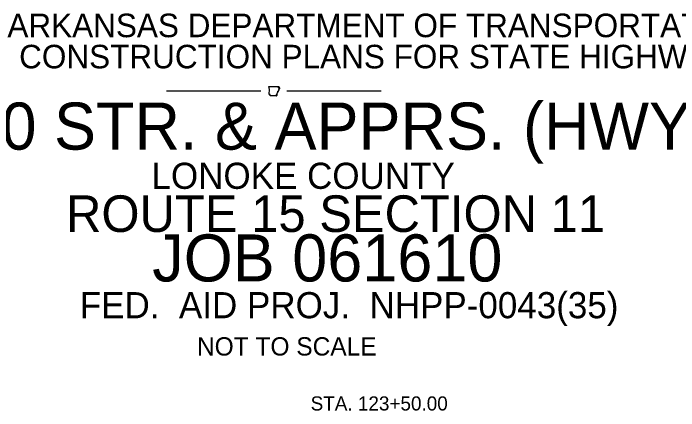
# Model space of a CAD drawing. Extents: x 1127717 to 1741049, y 2026793 to 2244711.
# Drawn here: x 1289221 to 1352785, y 2118754 to 2156746 of the extents above; entities that cross this region are included whole.
import ezdxf

# ---------------------------------------------------------------- set-up
doc = ezdxf.new("R2010")
doc.units = 0
doc.layers.add('R_Draft', color=7, linetype='Continuous')

msp = doc.modelspace()

# ---------------------------------------------------------------- linework, layer by layer
at = {"layer": 'R_Draft'}
for p, q in [((1303860.42359432, 2149337.5563738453), (1312860.4235955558, 2149337.5563738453)), ((1315360.42359432, 2149337.5563738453), (1324360.4235955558, 2149337.5563738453))]:
    msp.add_line(p, q, dxfattribs=at)
for points in [[(1313644.6151949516, 2149753.404178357), (1313917.4839450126, 2149753.2354283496), (1314156.9401949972, 2149753.7416783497), (1314439.4276950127, 2149758.129178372), (1314570.3776949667, 2149761.166678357)], [(1313664.358944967, 2149015.1229283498), (1313679.5464450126, 2149472.9416783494), (1313644.6151949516, 2149753.404178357)], [(1314529.8776949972, 2149629.372928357), (1314657.9589450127, 2149635.9541783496)], [(1314376.483944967, 2148850.4229283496), (1313758.015194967, 2148851.435428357), (1313757.6776950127, 2148987.9541783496)]]:
    msp.add_lwpolyline(points, dxfattribs=at)
for points in [[(1314570.3776949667, 2149761.166678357), (1314571.2214449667, 2149753.7416783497), (1314573.5839449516, 2149749.860428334), (1314573.9214450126, 2149742.7729283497), (1314576.7901950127, 2149739.7354283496), (1314581.6839449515, 2149736.697928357), (1314586.0714450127, 2149731.8041783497), (1314587.0839450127, 2149726.0666783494), (1314585.733944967, 2149720.160428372), (1314585.3964450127, 2149713.579178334), (1314584.7214449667, 2149707.841678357), (1314583.7089450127, 2149702.6104283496), (1314579.6589449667, 2149698.391678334), (1314575.7776950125, 2149695.3541783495), (1314572.2339450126, 2149691.8104283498), (1314569.7026950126, 2149688.0979283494), (1314565.3151949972, 2149684.047928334), (1314560.9276950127, 2149679.8291783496), (1314557.3839449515, 2149676.1166783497), (1314553.8401950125, 2149671.3916783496), (1314552.1526949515, 2149666.1604283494), (1314548.2714449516, 2149662.447928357), (1314545.233944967, 2149659.0729283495), (1314541.1839450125, 2149654.516678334), (1314539.1589449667, 2149649.9604283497), (1314535.2776949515, 2149644.7291783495), (1314534.4339449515, 2149639.666678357), (1314531.9026949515, 2149635.6166783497), (1314531.733944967, 2149634.9416783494)], [(1314518.5714450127, 2149306.2166783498), (1314514.6901949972, 2149301.322928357), (1314508.9526950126, 2149304.3604283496), (1314508.9526950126, 2149308.4104283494), (1314509.7964450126, 2149312.629178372), (1314507.7714450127, 2149315.3291783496), (1314504.2276950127, 2149314.147928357), (1314504.2276950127, 2149308.916678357), (1314503.8901950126, 2149303.8541783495), (1314502.8776949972, 2149296.5979283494), (1314505.2401949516, 2149294.404178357), (1314510.6401950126, 2149293.729178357), (1314514.5214449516, 2149292.716678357), (1314516.8839450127, 2149288.8354283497), (1314516.7151950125, 2149284.110428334), (1314514.8589450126, 2149279.5541783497), (1314512.1589449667, 2149275.8416783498), (1314507.9401949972, 2149274.4916783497), (1314504.5651949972, 2149276.6854283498), (1314503.2151949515, 2149281.0729283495), (1314501.6964450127, 2149284.9541783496), (1314498.827694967, 2149287.8229283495), (1314495.7901950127, 2149284.616678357), (1314495.1151950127, 2149278.7104283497), (1314495.2839449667, 2149273.6479283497), (1314495.2839449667, 2149266.7291783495), (1314499.671444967, 2149262.1729283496), (1314502.3714449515, 2149256.9416783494), (1314501.5276949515, 2149252.2166783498), (1314498.3214449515, 2149246.647928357), (1314496.9714449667, 2149241.7541783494), (1314495.6214450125, 2149235.1729283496), (1314495.7901950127, 2149227.916678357), (1314494.608944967, 2149220.8291783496), (1314492.2464449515, 2149216.1041783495), (1314487.858944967, 2149212.2229283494), (1314484.9901949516, 2149209.691678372), (1314482.6276949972, 2149207.1604283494), (1314481.4464449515, 2149202.097928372), (1314480.6026949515, 2149198.5541783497), (1314477.3964450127, 2149194.3354283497), (1314474.8651949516, 2149193.9979283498), (1314472.8401949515, 2149195.685428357), (1314472.1651950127, 2149198.5541783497), (1314472.1651950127, 2149201.422928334), (1314470.8151949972, 2149204.291678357), (1314466.5964449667, 2149205.4729283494), (1314463.2214449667, 2149205.3041783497), (1314461.7026950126, 2149202.9416783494), (1314463.8964450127, 2149196.3604283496), (1314464.7401950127, 2149192.1416783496), (1314463.5589449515, 2149186.4041783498), (1314464.233944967, 2149185.7291783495), (1314458.1589449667, 2149182.5229283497), (1314453.2651950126, 2149182.0166783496), (1314449.2151949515, 2149180.835428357), (1314445.3339449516, 2149178.3041783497), (1314443.4776950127, 2149174.591678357), (1314440.7776949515, 2149171.5541783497), (1314438.4151949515, 2149168.685428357), (1314435.2089450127, 2149167.3354283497), (1314431.6651950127, 2149168.010428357), (1314426.9401949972, 2149168.5166783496), (1314424.2401949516, 2149165.141678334), (1314425.0839449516, 2149160.247928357), (1314428.2901950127, 2149157.379178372), (1314433.0151950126, 2149156.0291783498), (1314437.9089449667, 2149156.3666783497), (1314442.6339450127, 2149156.8729283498), (1314447.0214450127, 2149154.5104283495), (1314446.1776949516, 2149149.954178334), (1314441.9589450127, 2149147.7604283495), (1314435.7151950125, 2149147.0854283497), (1314430.6526950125, 2149147.591678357), (1314424.5776950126, 2149146.2416783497), (1314421.5401949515, 2149142.360428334), (1314423.2276949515, 2149136.4541783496), (1314429.8089450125, 2149134.0916783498), (1314432.8464449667, 2149128.522928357), (1314433.0151950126, 2149123.291678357), (1314430.8214450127, 2149116.372928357), (1314427.7839449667, 2149113.166678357), (1314421.8776949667, 2149111.816678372), (1314417.3214449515, 2149110.9729283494), (1314416.6464449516, 2149103.2104283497), (1314414.6214449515, 2149099.3291783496), (1314411.077694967, 2149098.147928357), (1314406.015194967, 2149100.6791783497), (1314402.9776950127, 2149101.8604283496), (1314399.265194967, 2149103.5479283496), (1314394.5401949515, 2149106.416678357), (1314390.9964450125, 2149105.910428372), (1314392.0089449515, 2149098.485428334), (1314392.3464449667, 2149098.147928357), (1314396.3964449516, 2149092.5791783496), (1314400.4464450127, 2149088.1916783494), (1314402.3026949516, 2149082.9604283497)], [(1314591.8089449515, 2149473.4479283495), (1314592.4839450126, 2149468.5541783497), (1314589.6151950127, 2149463.322928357), (1314588.6026949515, 2149458.091678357), (1314589.108944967, 2149452.8604283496), (1314583.7089450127, 2149449.9916783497), (1314578.9839450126, 2149446.616678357), (1314581.6839449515, 2149442.5666783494), (1314586.7464450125, 2149438.854178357), (1314591.8089449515, 2149435.9854283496), (1314595.0151950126, 2149433.116678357), (1314595.8589450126, 2149426.197928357), (1314596.7026950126, 2149421.810428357), (1314598.3901950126, 2149415.7354283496), (1314599.0651949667, 2149411.5166783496), (1314596.0276949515, 2149406.4541783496), (1314592.4839450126, 2149405.4416783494), (1314588.7714450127, 2149406.622928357), (1314584.3839450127, 2149406.9604283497), (1314580.8401949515, 2149403.585428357), (1314578.3089450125, 2149398.8604283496), (1314575.7776950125, 2149394.1354283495), (1314573.9214450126, 2149390.0854283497), (1314572.0651949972, 2149385.6979283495), (1314568.3526949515, 2149380.635428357), (1314563.7964450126, 2149379.791678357), (1314558.3964450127, 2149378.441678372), (1314555.1901949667, 2149374.729178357), (1314555.6964450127, 2149368.4854283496), (1314558.733944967, 2149364.266678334), (1314561.0964449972, 2149359.0354283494), (1314562.7839449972, 2149354.4791783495), (1314561.9401949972, 2149348.7416783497), (1314559.577694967, 2149344.522928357), (1314556.5401949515, 2149341.9916783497), (1314555.1901949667, 2149336.591678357), (1314552.9964449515, 2149332.5416783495), (1314550.9714449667, 2149331.1916783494), (1314546.921444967, 2149331.529178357), (1314542.5339449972, 2149332.372928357), (1314538.8214449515, 2149332.0354283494), (1314535.2776949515, 2149330.1791783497), (1314531.733944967, 2149331.3604283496), (1314528.0214450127, 2149335.410428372), (1314524.983944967, 2149338.447928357), (1314521.6089450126, 2149339.6291783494), (1314518.0651949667, 2149337.7729283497), (1314517.390194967, 2149332.2041783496), (1314519.0776950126, 2149326.4666783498), (1314520.5964449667, 2149318.7041783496), (1314519.0776950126, 2149313.979178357), (1314518.5714450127, 2149306.2166783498)], [(1314656.1026949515, 2149635.7854283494), (1314657.9589450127, 2149635.9541783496), (1314663.6964450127, 2149629.8791783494), (1314666.2276950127, 2149624.816678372), (1314669.9401949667, 2149621.9479283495), (1314674.1589449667, 2149620.4291783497), (1314677.3651950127, 2149616.547928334), (1314679.5589449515, 2149612.3291783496), (1314678.3776949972, 2149608.6166783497), (1314673.6526950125, 2149608.2791783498), (1314668.4214450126, 2149607.4354283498), (1314663.358944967, 2149607.6041783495), (1314659.3089450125, 2149604.229178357), (1314663.0214449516, 2149599.6729283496), (1314667.9151950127, 2149595.454178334), (1314669.2651950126, 2149590.8979283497), (1314666.5651949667, 2149586.5104283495), (1314661.1651949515, 2149584.1479283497), (1314655.9339449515, 2149582.122928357), (1314651.2089450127, 2149578.0729283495), (1314649.015194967, 2149574.1916783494), (1314643.7839449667, 2149572.504178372), (1314638.3839450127, 2149570.9854283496), (1314633.6589449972, 2149570.4791783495), (1314628.2589449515, 2149569.466678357), (1314623.0276949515, 2149566.935428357), (1314620.8339450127, 2149562.5479283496), (1314621.5089450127, 2149556.3041783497), (1314621.3401949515, 2149549.722928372), (1314626.9089449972, 2149547.529178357), (1314631.8026949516, 2149547.3604283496), (1314636.5276950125, 2149544.8291783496), (1314636.0214449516, 2149541.1166783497), (1314632.4776949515, 2149536.3916783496), (1314628.2589449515, 2149532.6791783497), (1314624.0401949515, 2149530.822928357), (1314620.1589449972, 2149527.2791783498), (1314621.5089450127, 2149523.7354283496), (1314625.0526950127, 2149521.3729283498), (1314627.5839450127, 2149517.4916783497), (1314627.2464449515, 2149513.947928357), (1314623.1964449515, 2149511.4166783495), (1314618.8089449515, 2149512.4291783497), (1314615.6026950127, 2149516.6479283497), (1314611.890194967, 2149517.997928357), (1314608.6839450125, 2149519.5166783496), (1314604.9714449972, 2149517.3229283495), (1314604.9714449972, 2149512.4291783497), (1314603.6214450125, 2149507.197928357), (1314604.8026949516, 2149503.3166783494), (1314606.3214450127, 2149497.9166783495), (1314606.1526950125, 2149493.8666783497), (1314604.8026949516, 2149488.1291783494), (1314601.9339450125, 2149482.222928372), (1314598.5589450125, 2149480.3666783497), (1314597.2089450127, 2149486.779178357), (1314596.5339449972, 2149492.010428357), (1314594.5089449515, 2149495.0479283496), (1314591.8089449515, 2149495.216678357), (1314588.265194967, 2149492.685428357), (1314584.3839450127, 2149488.8041783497), (1314579.4901949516, 2149484.585428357), (1314576.6214450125, 2149480.3666783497), (1314578.1401950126, 2149475.1354283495), (1314581.8526950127, 2149473.7854283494), (1314584.7214449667, 2149474.7979283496), (1314586.2401950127, 2149478.1729283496), (1314589.108944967, 2149478.6791783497), (1314591.8089449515, 2149473.4479283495)], [(1313757.6776950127, 2148987.9541783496), (1313758.3526949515, 2148987.616678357), (1313755.1464450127, 2148989.810428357), (1313750.7589450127, 2148992.0041783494), (1313745.8651949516, 2148992.341678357), (1313739.6214450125, 2148993.1854283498), (1313734.3901950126, 2148993.691678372), (1313728.9901950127, 2148997.2354283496), (1313723.2526949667, 2148993.5229283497), (1313716.8401950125, 2148990.822928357), (1313713.1276949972, 2148993.8604283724), (1313708.2339450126, 2148991.8354283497), (1313704.8589450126, 2148992.847928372), (1313698.952694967, 2148988.7979283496), (1313693.3839450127, 2148990.3166783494), (1313689.3339449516, 2148989.135428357), (1313684.2714449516, 2148989.304178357), (1313683.2589449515, 2148995.041678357), (1313678.3651950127, 2148995.885428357), (1313674.1464449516, 2148998.247928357), (1313671.2776949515, 2149004.154178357), (1313669.2526949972, 2149008.7104283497), (1313664.358944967, 2149015.1229283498)], [(1314402.3026949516, 2149082.9604283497), (1314400.6151949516, 2149079.0791783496), (1314398.7589450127, 2149072.3291783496), (1314399.265194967, 2149066.5916783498), (1314401.7964450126, 2149061.697928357), (1314405.8464449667, 2149058.997928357), (1314410.233944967, 2149055.116678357), (1314409.8964450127, 2149049.2104283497), (1314407.3651950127, 2149047.0166783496), (1314401.4589449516, 2149048.5354283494), (1314396.9026950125, 2149050.560428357), (1314393.0214449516, 2149049.3791783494), (1314387.7901949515, 2149046.847928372), (1314383.9089449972, 2149046.3416783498), (1314384.077694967, 2149038.2416783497), (1314389.3089449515, 2149032.5041783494), (1314393.8651949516, 2149032.5041783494), (1314399.0964449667, 2149031.829178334), (1314400.9526950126, 2149025.7541783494), (1314397.9151950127, 2149020.6916783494), (1314392.8526949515, 2149018.1604283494), (1314386.4401949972, 2149021.1979283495), (1314381.8839450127, 2149024.4041783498), (1314377.327694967, 2149027.4416783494), (1314371.5901950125, 2149028.9604283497), (1314368.3839450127, 2149028.2854283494), (1314366.8651949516, 2149021.1979283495), (1314369.5651949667, 2149014.7854283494), (1314373.9526950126, 2149010.397928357), (1314378.0026949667, 2149004.6604283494), (1314377.327694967, 2149000.441678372), (1314374.2901950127, 2148999.2604283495), (1314368.890194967, 2148998.0791783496), (1314365.6839450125, 2148996.3916783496), (1314364.8401950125, 2148995.041678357), (1314366.5276950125, 2148989.304178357), (1314368.046444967, 2148983.060428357), (1314368.046444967, 2148978.3354283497), (1314366.1901949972, 2148973.947928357), (1314363.3214449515, 2148967.197928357), (1314363.6589449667, 2148962.8104283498), (1314365.6839450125, 2148960.7854283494), (1314368.2151950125, 2148961.4604283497), (1314371.5901950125, 2148963.8229283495), (1314373.7839449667, 2148966.522928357), (1314375.640194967, 2148969.8979283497), (1314379.1839450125, 2148972.7666783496), (1314383.5714450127, 2148970.2354283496), (1314384.5839450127, 2148965.004178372), (1314382.0526950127, 2148960.447928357), (1314378.5089450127, 2148958.4229283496), (1314374.1214449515, 2148956.7354283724), (1314370.9151950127, 2148953.0229283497), (1314371.7589450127, 2148948.6354283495), (1314374.2901950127, 2148946.2729283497), (1314380.5339449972, 2148947.4541783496), (1314384.7526949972, 2148949.3104283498), (1314387.1151949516, 2148951.6729283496), (1314389.9839450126, 2148954.5416783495), (1314391.5026949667, 2148957.410428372), (1314393.6964449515, 2148960.447928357), (1314397.577694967, 2148961.291678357), (1314399.4339450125, 2148958.760428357), (1314398.7589450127, 2148953.0229283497), (1314396.3964449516, 2148947.622928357), (1314393.1901949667, 2148943.066678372), (1314389.6464450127, 2148939.8604283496), (1314385.2589450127, 2148932.9416783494), (1314386.1026950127, 2148926.5291783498), (1314387.7901949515, 2148921.2979283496), (1314390.1526949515, 2148917.247928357), (1314394.2026950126, 2148918.091678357), (1314398.7589450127, 2148918.597928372), (1314401.4589449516, 2148916.404178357), (1314401.1214450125, 2148911.6791783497), (1314397.7464450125, 2148907.122928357), (1314394.5401949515, 2148902.7354283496), (1314392.8526949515, 2148896.660428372), (1314393.5276950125, 2148892.4416783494), (1314393.5276950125, 2148888.560428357), (1314392.1776949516, 2148884.341678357), (1314389.8151949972, 2148881.9791783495), (1314383.5714450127, 2148882.1479283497), (1314376.9901950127, 2148882.822928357), (1314373.4464450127, 2148880.7979283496), (1314374.1214449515, 2148875.0604283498), (1314378.0026949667, 2148870.841678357), (1314380.702694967, 2148868.647928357), (1314384.5839450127, 2148863.9229283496), (1314386.2714449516, 2148860.0416783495), (1314385.7651950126, 2148856.666678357), (1314383.4026949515, 2148853.797928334), (1314376.483944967, 2148850.4229283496)]]:
    msp.add_spline(points, degree=3, dxfattribs=at)

# ---------------------------------------------------------------- texts
for s, height, p in [('ARKANSAS DEPARTMENT OF TRANSPORTATION', 2249.999999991, (1288655.9452484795, 2154462.5563732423)), ('CONSTRUCTION PLANS FOR STATE HIGHWAY', 2249.999999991, (1289777.2543035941, 2151482.5563732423)), ('I-40 STR. & APPRS. (HWY. 15) (S)', 4500, (1281068.100760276, 2143712.556373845)), ('LONOKE COUNTY', 2500, (1302421.4472169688, 2139962.556373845)), ('ROUTE 15 SECTION 11', 3499.9999999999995, (1294258.0613902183, 2135840.4989236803)), ('JOB 061610', 4500, (1302492.313358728, 2131107.599422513)), ('FED.  AID PROJ.  NHPP-0043(35)', 2500, (1295571.0535161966, 2127591.5978559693)), ('NOT TO SCALE', 1749.9999999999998, (1306765.9354059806, 2124029.1500511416)), ('STA. 123+50.00', 1349.9999999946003, (1317625.6824788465, 2118772.688250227))]:
    msp.add_text(s, height=height, dxfattribs=at).set_placement(p)

doc.saveas('drawing.dxf')
